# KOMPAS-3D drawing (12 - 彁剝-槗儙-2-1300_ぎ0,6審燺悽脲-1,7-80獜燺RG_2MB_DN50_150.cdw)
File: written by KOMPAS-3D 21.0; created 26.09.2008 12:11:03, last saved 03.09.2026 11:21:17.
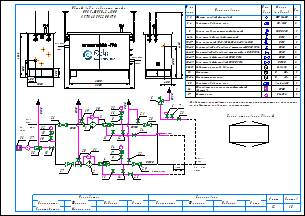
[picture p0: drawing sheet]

Sheets 1-2: A3, landscape

Document properties: Наименование: Макро:21; Автор: RaskoAdmin; Форматы листов документа: 2xA3; Полное имя файла: \\UR38nt01\Departments\КТО\КБ ПУРДГ\Заявки\Прайс-лист на типовые шкафы ГРПШ\ПРДГ_стандарт_20_03_2026\ПРДГ с RG_2MB\ПРДГ-ШУГО-2-1300_до0,6МПа_Рвых-1,7-80кПа_RG_2MB_DN50_150.cdw

Title block, sheet 1: Наименование: Пункт учета газа / ПУГ-Ш-400-Р / ЛГТИ.485922.001ТУ; designation: ЛГТИ.03.4411141; sheet number: 1; Количество листов документа: 2; organisation: ООО "ЭЛЬСТЕР Газэлектроника"; Форматы листов документа: A3; stored path: C:\Рабочие документы\Компас\ПУГ\Схема.cdw; Разработал: Устинов; Проверил: Кошкин; Утвердил: Кошкин
Title block, sheet 2: sheet number: 2; stored path: D:\Рабочие документы\Заявки\ПУРДГ\ПУРДГ-ШУЭО-2-100-Р 4411220.cdw; designation, second copy: ЛГТИ.03.4411141-

Views: Вид 1, Вид 2
Referenced files: wcvoit.frw
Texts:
  Normal
  Вход
  газа
  PDI
  Выход
  Р=     кПа
  DN150
  DN50
  DN20
  Импульс DN20
  ≥5DN
  HYSWLongFangSong
  Общий вид и габариты шкафа
  ПРДГ-ШУГО-2-1300
  Выход газа
  Вход газа
  Р=        МПа
  logo-rasko-ge.png
  № на
  схеме
  Усл.
  обозн.
  Марка
  (модель)
  Кол.
  Фильтр газовый фланцевый
  ФГ 16-50
  Регулятор давления газа
  RG/2MB
  Клапан предохранительный сбросной
  КПС DN20
  Кран шаровой газовый латунный
  DN15
  Кран кнопочный VE-РАСКО-НЗ-1,6-G1/2-М20
  Кран шаровой "под приварку" штуцерный DN20 PN16
  Кран шаровой "под приварку" штуцерный п/п DN20 PN16
  Кран шаровой фланцевый DN50 PN16
  Кран шаровой фланцевый DN150 PN16
  Индикатор перепада давления
  Delta 15
  Манометр
  Манометр-напоромер
  0...     МПа
  0...     кПа
  Обогреватель газогорелочный шкафной
  (Эльтон")
  Счетчик газа
  Venio-A-15
  ОГШН
  BK-G1,6
  Схема открывания дверей
  Предприятие изготовитель может заменять комплектующие на аналогичные,
  не ухудшающие заявленных характеристик.
  Должность
  Конструктор
  Фамилия
  Подпись
  Дата
  Согласовано
  Максимкин
  Лист
  Листов
  POLYLINE_STYLE_0.18_RGB_0_0_0
  POLYLINE_STYLE_0.50_RGB_0_0_0
  POLYLINE_STYLE_0.34_RGB_0_0_0
  PHANTOM_RGB_0_0_0_SC_1_THICK_0.18
  K5LT_THIN_RGB_0_0_0_THICK_0.18
  K5LT32769_RGB_0_0_0_THICK_0.18
  K5LT12_RGB_0_0_0_SC_1_THICK_0.18
  K5LT_DASHED_RGB_0_0_0_SC_1_THICK_0.18
  ACISOTGL_RGB_0_0_0_SC_0.8_THICK_0.25
  CONTINUOUS_RGB_0_127_31_THICK_0.3
  CONTINUOUS_RGB_0_0_255_THICK_0.35
  CONTINUOUS_RGB_255_0_0_THICK_0.35
  POLYLINE_STYLE_0.25_RGB_0_0_0
  CONTINUOUS_RGB_0_0_0_THICK_0.5
  POLYLINE_STYLE_0.35_RGB_0_0_255
  CONTINUOUS_RGB_0_0_0_THICK_0.4
  CONTINUOUS_RGB_0_0_0_THICK_0.35
  Без оформления
Dimensions and other numbers on the sheet: 1; 2; 3; 4; 5; 10; 27; 28; 29; 23; 8; 12; 19; 20; 21; 22; 25; 24; 30; 31; 15; 16; 26; 6; 7; 11; 14; 13; 33; 400; 1050; 500; 305; 2500; 1565; 32; 2800; 9; 17; 34; 1000; 4130; 1, 2; 3, 4; 6-14; 15-17; 18-23; 24-25; 26-27; 28-29; 30-31; 33-34; 35; 36; 37; 18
